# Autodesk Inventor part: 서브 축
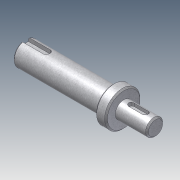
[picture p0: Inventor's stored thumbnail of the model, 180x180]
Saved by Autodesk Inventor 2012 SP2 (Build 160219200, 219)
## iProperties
Company: 한국ATC센터
Created: 2014-10
Part Number: 서브 축
Document SubType Name: Modeling
Designer: KYOUNG IL JANG
Density: 1 g/cm^3
Mass: 19.9624 g
Surface Area: 57.7178 cm^2
Volume: 19.9624 cm^3
Material: 기본값
Author: KYOUNG IL JANG
Revision Number: 1
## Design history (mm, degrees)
sketch "스케치1"
  geometry: L1 (-16.331, 0)-(-108.831, 0); L2 (-16.331, 0)-(-16.331, -6); L3 (-16.331, -6)-(-38.831, -6); L4 (-38.831, -12.5)-(-46.5, -12.5); L5 (-46.5, -8.5)-(-108.831, -8.5); L6 (-108.831, -8.5)-(-108.831, 0); L7 (-46.5, -8.5)-(-46.5, -12.5); L8 (-38.831, -6)-(-38.831, -12.5); L9 (-46.5, 12.249)-(-46.5, -12.249) reference; L10 (-38.831, -17)-(-38.831, 17) reference; 2 further points
  constraints: 17 end point, 4 perpendicular, 2 collinear, 2 parallel, 1 horizontal, 1 midpoint, 1 point on line
  dimensions: "d1" = 12 diameter of L3 L1; "d2" = 25 diameter of L4 L1; "d3" = 17 diameter of L5 L1; "d4" = 62.33128 distance of L5.start L5.end (derived); "d18" = 22.5 distance of L2.end L3.end; "d20" = 70 distance between parallel lines of L6 L8
revolve "회전1" sketch "스케치1" stored, may be unused: angle "d5" = 90 deg
chamfer "모따기1" distance "d6" = 1; stored, may be unused: second distance "d7" = 2, angle "d8" = 45 deg
node "작업 평면1"
sketch "스케치2"
  geometry: L1 (11.25, 5)-(11.25, -5) reference; L2 (-5.75, -2)-(4.25, -2); L3 (4.25, 2)-(-5.75, 2); A1 r 2 centre (4.25, 0) between (4.25, -2) and (4.25, 2); A2 r 2 centre (-5.75, 0) between (-5.75, 2) and (-5.75, -2); 2 further points
  constraints: 4 end point, 4 point on circle, 4 tangent, 2 centre point, 1 horizontal alignment, 1 midpoint, 1 parallel, 1 perpendicular
  dimensions: "d9" = 4 distance between parallel lines of L2 L3; "d10" = 14 dimension on A1 A2; "d11" = 5 distance edge to line of A1 L1
extrude "돌출1" cut sketch "스케치2" distance "d12" = 2.5; taper "d13" = 0 deg
node "작업 평면2"
sketch "스케치3"
  geometry: L1 (-31.166, -7.5)-(-31.166, 7.5) reference; L2 (-31.166, 2.5)-(-15.666, 2.5); L3 (-15.666, -2.5)-(-31.166, -2.5); A1 r 2.5 centre (-15.666, 0) between (-15.666, -2.5) and (-15.666, 2.5); 2 further points
  constraints: 4 end point, 2 perpendicular, 2 point on circle, 2 point on line, 2 tangent, 1 centre point, 1 horizontal alignment, 1 midpoint
  dimensions: "d14" = 5 distance between parallel lines of L3 L2; "d15" = 18 dimension on A1 L1
extrude "돌출2" cut sketch "스케치3" distance "d16" = 3; taper "d17" = 0 deg
node "솔리드1"
node "참조4"
node "참조5"
